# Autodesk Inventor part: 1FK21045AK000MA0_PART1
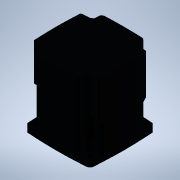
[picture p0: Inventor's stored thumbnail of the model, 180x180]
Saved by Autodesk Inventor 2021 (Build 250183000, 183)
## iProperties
Created: 2025-04
Part Number: 1FK21045AK000MA0_PART1
Material: Generic
Catalog Web Link: www.3dfindit.com
Description: -Servo synchronous motor
Document SubType Name: Modeling
Designer: psAdmin
Mass: 473.602 g
Surface Area: 436.509 cm^2
Volume: 473.602 cm^3
Density: 1 g/cm^3
Appearance: PSOLRGB-176-176-176
Category: PARTsolutions
Title: 1FK21045AK000MA0_PART1
Author: Cadenas PARTsolutions
Comments: Servo synchronous motor
Sending System: PARTsolutions
Preprocessor: ST-DEVELOPER v19.3
PSOL_IDENT_0: {$CADENAS_DATA/23d-libs/siemens_ag/_cat_/3d/2f/1fk21045ak000ma0.prj},213 {VTYP=3D},{NB=1FK21045AK000
PSOL_IDENT_1: MA0_PART1},{LINA=1FK21045AK000MA0_PART1},{NN=1FK21045AK000MA0_PART1},{NOPRJ=TRUE},{DATE=19.08.2025 1
PSOL_IDENT_2: 4:00:34},{GEOMDATE=30.07.2025 02:01:24},{VERSION=},{LINEID=10},{WBVAR=},{WBNUMERIC=}  {NB=1FK21045AK
PSOL_IDENT_3: 000MA0_PART1},{LINA=1FK21045AK000MA0_PART1},{KT=DUMMY},{PREVIEW=../../../_pool_/a9/69/p_d211_xx_0081
PSOL_IDENT_4: 8j.png},{DESCSHORT=SIMOTICS S-1FK2 HD, SINAMICS S210 3AC 400V-480V, 1.7 Nm, 6000 rpm},{DESCLONG=SIMO
PSOL_IDENT_5: TICS S-1FK2 HD servo motor M0=2.4 Nm; PN = 1.07 kW at nN=6000 rpm (380-480 V); PN = 0.75 kW at nN=30
PSOL_IDENT_6: 00 rpm (200-240 V); degree of protection IP64; cylindrical shaft D19x40mm; absolute encoder 22-bit +
PSOL_IDENT_7: 12-bit multiturn (encoder AM22DQC); with OCC interface; plug size M17, rotatable; SIMOTICS S-1FK2 s
PSOL_IDENT_8: ervomotorfor a wide range of uses in industrial environments. SIMOTICS S‑1FK2 servomotors are compac
PSOL_IDENT_9: t synchronous motors with a high dynamic performance that set themselves apart as a result of their
PSOL_IDENT_10: high power density, degree of protection and overload capability. The motors are available in two va
PSOL_IDENT_11: riants: as High Dynamic variant (highest dynamic performance as a result of the low intrinsic moment
PSOL_IDENT_12: of inertia for applications demanding a high dynamic performance with low moved masses) - and as Co
PSOL_IDENT_13: mpact variant (precise and stable closed-loop control for medium up to large moved masses as a resul
PSOL_IDENT_14: t of a medium intrinsic moment of inertia). SIMOTICSS‑1FK2 servomotors fully exploit their strengths
PSOL_IDENT_15: in a system with the SINAMICSS210 frequency converter and simple connection using the one cable con
PSOL_IDENT_16: nection (OCC). Advantages include the short control and positioning times, fast and precise correcti
PSOL_IDENT_17: on of disturbing quantities as well as stable control with a high dynamic performance. The servo mot
PSOL_IDENT_18: ors can be configured to address a wide range of requirements. For example with and without holding
PSOL_IDENT_19: brake, IP64 or IP65 degree of protection, singleturn or multiturn absolute encoders - to name just a
PSOL_IDENT_20: few. Further, the servomotors are available in different shaft heights extending from 20 to 100. A
PSOL_IDENT_21: shaft sealing ring is available to achieve an IP65 degree of protection and for subsequent mounting
PSOL_IDENT_22: at the motor or as spare part. SIMOTICS - the optimum motor for each and every motion control applic
PSOL_IDENT_23: ation.},{INTNO=804766789342},{SUPPLIERALTNO=1FK2104-5AK00-0MA0},{MANUID=1FK21045AK000MA0},{MANUNAME=
PSOL_IDENT_24: Siemens},{MANUTYPEDESC=Synchronous motor 1FK2-HD 2,39 Nm},{AAU732=SIMOTICS},{AAO057=S-1FK2},{AAU734=
PSOL_IDENT_25: SIMOTICS S-1FK2 HD servo motor M0=2.4 Nm; PN = 1.07 kW at nN=6000 rpm (380-480 V); PN = 0.75 kW at n
PSOL_IDENT_26: N=3000 rpm (200-240 V); degree of protection IP64; cylindrical shaft D19x40mm; absolute encoder 22-b
PSOL_IDENT_27: it + 12-bit multiturn (encoder AM22DQC); with OCC interface; plug size M17, rotatable;},{AAW338=Sync
PSOL_IDENT_28: hronous motor 1FK2-HD 2,39 Nm},{AAO742=SIMOTICS},{AAO663=4042948691151},{NOCUPEROU=1},{PRICEQUANTITY=
PSOL_IDENT_29: 1},{QUANTITYMIN=1},{QUANTITYINT=1},{CTN=85015100},{COO=DE},{AAO676=1FK2104-5AK00-0MA0},{AAO677=Sieme
PSOL_IDENT_30: ns AG},{ORDERUNIT=C62},{CONTENTUNIT=C62}
NB: 1FK21045AK000MA0_PART1
NT: Servo synchronous motor
NBSYN: $MANUID._PART1
LINA: 1FK21045AK000MA0_PART1
CATALOG: SIEMENS
PREVIEW: ../../../_pool_/a9/69/p_d211_xx_00818j.png
DESCSHORT: SIMOTICS S-1FK2 HD, SINAMICS S210 3AC 400V-480V, 1.7 Nm, 6000 rpm
DESCLONG: SIMOTICS S-1FK2 HD servo motor M0=2.4 Nm; PN = 1.07 kW at nN=6000 rpm (380-480 V); PN = 0.75 kW at nN=3000 rpm (200-240 V); degree of protection IP64; cylindric
INTNO: 804766789342
SUPPLIERALTNO: 1FK2104-5AK00-0MA0
MANUID: 1FK21045AK000MA0
MANUNAME: Siemens
MANUTYPEDESC: Synchronous motor 1FK2-HD 2,39 Nm
AAU732: SIMOTICS
AAO057: S-1FK2
AAU734: SIMOTICS S-1FK2 HD servo motor M0=2.4 Nm; PN = 1.07 kW at nN=6000 rpm (380-480 V); PN = 0.75 kW at nN=3000 rpm (200-240 V); degree of protection IP64; cylindric
AAW338: Synchronous motor 1FK2-HD 2,39 Nm
AAO742: SIMOTICS
AAO663: 4042948691151.0
NOCUPEROU: 1
PRICEQUANTITY: 1
QUANTITYMIN: 1
QUANTITYINT: 1
CTN: 85015100
COO: DE
ARTICLENO: 1FK21045AK000MA0_PART1
BOMINFO: 1FK21045AK000MA0_PART1
CREATOR: CADENAS GmbH
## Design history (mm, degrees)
feature "2025_04_17_15_39_51_0572"
node "ECLASS_CAX_IMPORTER_001_CP_0_XY"
node "ECLASS_CAX_IMPORTER_001_CP_0_YZ"
node "ECLASS_CAX_IMPORTER_001_CP_0_ZX"
node "ECLASS_CAX_IMPORTER_001_CP_0_X"
node "ECLASS_CAX_IMPORTER_001_CP_0_Y"
node "ECLASS_CAX_IMPORTER_001_CP_0_Z"
node "ECLASS_CAX_IMPORTER_001_CP_0_Center"
node "ECLASS_CAX_IMPORTER_001_CP_1_XY"
node "ECLASS_CAX_IMPORTER_001_CP_1_YZ"
node "ECLASS_CAX_IMPORTER_001_CP_1_ZX"
node "ECLASS_CAX_IMPORTER_001_CP_1_X"
node "ECLASS_CAX_IMPORTER_001_CP_1_Y"
node "ECLASS_CAX_IMPORTER_001_CP_1_Z"
node "ECLASS_CAX_IMPORTER_001_CP_1_Center"
body "Solid1"
